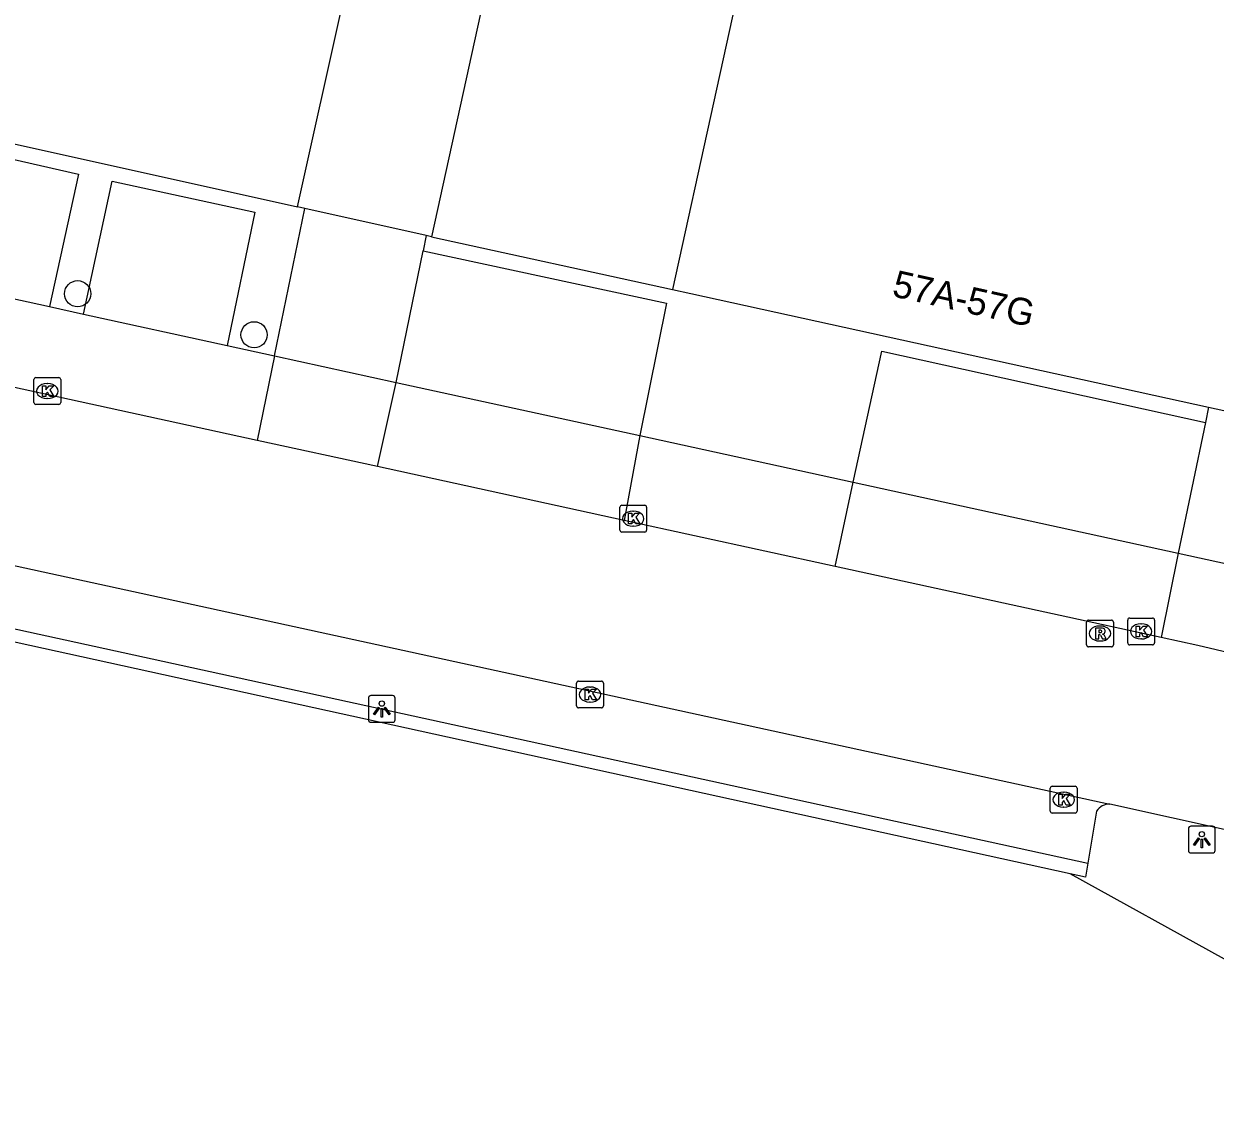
# Model space of a CAD drawing. Extents: x 163010 to 163853, y 382793 to 383982.
# Drawn here: x 163213.7 to 163258.14, y 382852.68 to 382893.41 of the extents above; entities that cross this region are included whole.
import ezdxf

# ---------------------------------------------------------------- set-up
doc = ezdxf.new("R2010")
doc.units = 0
for name, color, linetype in [('IMGEO_Boom', 7, 'Continuous'), ('IMGEO_Kademuur', 7, 'Continuous'), ('IMGEO_Kolk', 7, 'Continuous'), ('IMGEO_Lichtpunt', 7, 'Continuous'), ('IMGEO_Pand', 7, 'Continuous'), ('IMGEO_Pand_nummerreeks', 7, 'Continuous'), ('IMGEO_Parkeervlak_open', 7, 'Continuous'), ('IMGEO_Rijbaan_lokaal_open', 7, 'Continuous'), ('IMGEO_Rioolput', 7, 'Continuous'), ('IMGEO_Voetpad_open', 7, 'Continuous'), ('IMGEO_Waterloop', 7, 'Continuous')]:
    doc.layers.add(name, color=color, linetype=linetype)

msp = doc.modelspace()

# ---------------------------------------------------------------- linework, layer by layer
at = {"layer": 'IMGEO_Boom'}
for centre in [(163215.704, 382883.335), (163222.286, 382881.804)]:
    msp.add_circle(centre, 0.489, dxfattribs=at)
at = {"layer": 'IMGEO_Kademuur'}
for points in [[(163252.738, 382861.689), (163209.827, 382871.108), (163204.433, 382869.162), (163201.933, 382869.794), (163192.517, 382871.853), (163191.906, 382871.987), (163186.047, 382873.165), (163185.933, 382872.633), (163174.194, 382875.226), (163171.373, 382875.849), (163171.404, 382875.989), (163170.403, 382876.218), (163170.06, 382876.294)], [(163209.526, 382871.666), (163253.391, 382862.084)], [(163253.391, 382862.084), (163253.303, 382861.565), (163252.738, 382861.689)]]:
    msp.add_lwpolyline(points, dxfattribs=at)
at = {"layer": 'IMGEO_Kolk'}
for p, q in [((163214.072, 382879.279), (163214.072, 382880.131)), ((163214.147, 382880.205), (163214.999, 382880.205)), ((163215.073, 382880.131), (163215.073, 382879.279)), ((163214.56, 382879.985), (163214.585, 382879.985)), ((163214.999, 382879.205), (163214.147, 382879.205)), ((163214.583, 382879.425), (163214.558, 382879.425)), ((163235.931, 382874.518), (163235.931, 382875.37)), ((163236.006, 382875.444), (163236.858, 382875.444)), ((163236.419, 382875.224), (163236.444, 382875.224)), ((163236.932, 382875.37), (163236.932, 382874.518)), ((163236.858, 382874.444), (163236.006, 382874.444)), ((163236.442, 382874.664), (163236.417, 382874.664)), ((163254.954, 382871.234), (163255.806, 382871.234)), ((163254.879, 382870.308), (163254.879, 382871.16)), ((163255.367, 382871.014), (163255.392, 382871.014)), ((163255.88, 382871.16), (163255.88, 382870.308)), ((163255.39, 382870.454), (163255.365, 382870.454)), ((163255.806, 382870.234), (163254.954, 382870.234)), ((163234.318, 382867.954), (163234.318, 382868.806)), ((163234.393, 382868.88), (163235.245, 382868.88)), ((163234.806, 382868.66), (163234.831, 382868.66)), ((163235.319, 382868.806), (163235.319, 382867.954)), ((163234.829, 382868.1), (163234.804, 382868.1)), ((163235.245, 382867.88), (163234.393, 382867.88)), ((163251.991, 382864.03), (163251.991, 382864.882)), ((163252.066, 382864.956), (163252.918, 382864.956)), ((163252.479, 382864.736), (163252.504, 382864.736)), ((163252.992, 382864.882), (163252.992, 382864.03)), ((163252.502, 382864.176), (163252.477, 382864.176)), ((163252.918, 382863.956), (163252.066, 382863.956))]:
    msp.add_line(p, q, dxfattribs=at)
for points in [[(163214.072, 382879.279), (163214.072, 382880.131)], [(163214.147, 382880.205), (163214.999, 382880.205)], [(163215.073, 382880.131), (163215.073, 382879.279)], [(163214.393, 382879.905), (163214.516, 382879.905), (163214.516, 382879.754), (163214.646, 382879.905), (163214.81, 382879.905), (163214.664, 382879.754), (163214.817, 382879.505), (163214.665, 382879.505), (163214.58, 382879.669), (163214.516, 382879.602), (163214.516, 382879.505), (163214.393, 382879.505), (163214.393, 382879.905)], [(163214.999, 382879.205), (163214.147, 382879.205)], [(163235.931, 382874.518), (163235.931, 382875.37)], [(163236.006, 382875.444), (163236.858, 382875.444)], [(163236.932, 382875.37), (163236.932, 382874.518)], [(163236.252, 382875.144), (163236.375, 382875.144), (163236.375, 382874.993), (163236.505, 382875.144), (163236.669, 382875.144), (163236.523, 382874.993), (163236.676, 382874.744), (163236.524, 382874.744), (163236.439, 382874.908), (163236.375, 382874.841), (163236.375, 382874.744), (163236.252, 382874.744), (163236.252, 382875.144)], [(163236.858, 382874.444), (163236.006, 382874.444)], [(163254.954, 382871.234), (163255.806, 382871.234)], [(163254.879, 382870.308), (163254.879, 382871.16)], [(163255.2, 382870.934), (163255.323, 382870.934), (163255.323, 382870.783), (163255.453, 382870.934), (163255.617, 382870.934), (163255.471, 382870.783), (163255.624, 382870.534), (163255.472, 382870.534), (163255.387, 382870.698), (163255.323, 382870.631), (163255.323, 382870.534), (163255.2, 382870.534), (163255.2, 382870.934)], [(163255.88, 382871.16), (163255.88, 382870.308)], [(163255.806, 382870.234), (163254.954, 382870.234)], [(163234.318, 382867.954), (163234.318, 382868.806)], [(163234.393, 382868.88), (163235.245, 382868.88)], [(163234.639, 382868.58), (163234.762, 382868.58), (163234.762, 382868.429), (163234.892, 382868.58), (163235.056, 382868.58), (163234.91, 382868.429), (163235.063, 382868.18), (163234.911, 382868.18), (163234.826, 382868.344), (163234.762, 382868.277), (163234.762, 382868.18), (163234.639, 382868.18), (163234.639, 382868.58)], [(163235.319, 382868.806), (163235.319, 382867.954)], [(163235.245, 382867.88), (163234.393, 382867.88)], [(163251.991, 382864.03), (163251.991, 382864.882)], [(163252.066, 382864.956), (163252.918, 382864.956)], [(163252.312, 382864.656), (163252.435, 382864.656), (163252.435, 382864.505), (163252.565, 382864.656), (163252.729, 382864.656), (163252.583, 382864.505), (163252.736, 382864.256), (163252.584, 382864.256), (163252.499, 382864.42), (163252.435, 382864.353), (163252.435, 382864.256), (163252.312, 382864.256), (163252.312, 382864.656)], [(163252.992, 382864.882), (163252.992, 382864.03)], [(163252.918, 382863.956), (163252.066, 382863.956)]]:
    msp.add_lwpolyline(points, dxfattribs=at)
for centre, start, end in [((163214.149, 382880.129), 91.552, 178.448), ((163214.149, 382880.129), 91.552, 178.448), ((163214.997, 382880.129), 1.552, 88.448), ((163214.997, 382880.129), 1.552, 88.448), ((163214.149, 382879.281), 181.552, 268.448), ((163214.149, 382879.281), 181.552, 268.448), ((163214.997, 382879.281), 271.552, 358.448), ((163214.997, 382879.281), 271.552, 358.448), ((163236.008, 382875.368), 91.552, 178.448), ((163236.008, 382875.368), 91.552, 178.448), ((163236.856, 382875.368), 1.552, 88.448), ((163236.856, 382875.368), 1.552, 88.448), ((163236.008, 382874.52), 181.552, 268.448), ((163236.008, 382874.52), 181.552, 268.448), ((163236.856, 382874.52), 271.552, 358.448), ((163236.856, 382874.52), 271.552, 358.448), ((163254.956, 382871.158), 91.552, 178.448), ((163254.956, 382871.158), 91.552, 178.448), ((163255.804, 382871.158), 1.552, 88.448), ((163255.804, 382871.158), 1.552, 88.448), ((163254.956, 382870.31), 181.552, 268.448), ((163254.956, 382870.31), 181.552, 268.448), ((163255.804, 382870.31), 271.552, 358.448), ((163255.804, 382870.31), 271.552, 358.448), ((163234.395, 382868.804), 91.552, 178.448), ((163234.395, 382868.804), 91.552, 178.448), ((163235.243, 382868.804), 1.552, 88.448), ((163235.243, 382868.804), 1.552, 88.448), ((163234.395, 382867.956), 181.552, 268.448), ((163234.395, 382867.956), 181.552, 268.448), ((163235.243, 382867.956), 271.552, 358.448), ((163235.243, 382867.956), 271.552, 358.448), ((163252.068, 382864.88), 91.552, 178.448), ((163252.068, 382864.88), 91.552, 178.448), ((163252.916, 382864.88), 1.552, 88.448), ((163252.916, 382864.88), 1.552, 88.448), ((163252.068, 382864.032), 181.552, 268.448), ((163252.068, 382864.032), 181.552, 268.448), ((163252.916, 382864.032), 271.552, 358.448), ((163252.916, 382864.032), 271.552, 358.448)]:
    msp.add_arc(centre, 0.0765, start, end, dxfattribs=at)
for centre, major_axis, ratio, start_param, end_param in [((163214.559, 382879.705), (-0.387, 0.002), 0.722429, 4.712389, 7.853982), ((163214.584, 382879.705), (-0.39, 0.002), 0.717154, 1.570796, 4.712389), ((163236.418, 382874.944), (-0.387, 0.002), 0.722429, 4.712389, 7.853982), ((163236.443, 382874.944), (-0.39, 0.002), 0.717154, 1.570796, 4.712389), ((163255.366, 382870.734), (-0.387, 0.002), 0.722429, 4.712389, 7.853982), ((163255.391, 382870.734), (-0.39, 0.002), 0.717154, 1.570796, 4.712389), ((163234.805, 382868.38), (-0.387, 0.002), 0.722429, 4.712389, 7.853982), ((163234.83, 382868.38), (-0.39, 0.002), 0.717154, 1.570796, 4.712389), ((163252.478, 382864.456), (-0.387, 0.002), 0.722429, 4.712389, 7.853982), ((163252.503, 382864.456), (-0.39, 0.002), 0.717154, 1.570796, 4.712389)]:
    msp.add_ellipse(centre, major_axis=major_axis, ratio=ratio, start_param=start_param, end_param=end_param, dxfattribs=at)
at = {"layer": 'IMGEO_Lichtpunt'}
for p, q in [((163226.554, 382868.245), (163226.554, 382867.438)), ((163226.554, 382868.245), (163226.554, 382867.438)), ((163227.456, 382868.34), (163226.648, 382868.34)), ((163227.456, 382868.34), (163226.648, 382868.34)), ((163227.55, 382867.438), (163227.55, 382868.245)), ((163227.55, 382867.438), (163227.55, 382868.245)), ((163226.648, 382867.344), (163227.456, 382867.344)), ((163226.648, 382867.344), (163227.456, 382867.344)), ((163257.146, 382863.37), (163257.146, 382862.563)), ((163257.146, 382863.37), (163257.146, 382862.563)), ((163258.048, 382863.465), (163257.24, 382863.465)), ((163258.048, 382863.465), (163257.24, 382863.465)), ((163258.142, 382862.563), (163258.142, 382863.37)), ((163258.142, 382862.563), (163258.142, 382863.37)), ((163257.24, 382862.469), (163258.048, 382862.469)), ((163257.24, 382862.469), (163258.048, 382862.469))]:
    msp.add_line(p, q, dxfattribs=at)
for points in [[(163226.928, 382867.909), (163226.967, 382867.881), (163226.779, 382867.619), (163226.741, 382867.646), (163226.928, 382867.909)], [(163227.03, 382867.861), (163227.077, 382867.861), (163227.077, 382867.539), (163227.03, 382867.539), (163227.03, 382867.861)], [(163227.14, 382867.881), (163227.178, 382867.908), (163227.365, 382867.646), (163227.326, 382867.618), (163227.14, 382867.881)], [(163257.52, 382863.034), (163257.559, 382863.006), (163257.371, 382862.744), (163257.333, 382862.771), (163257.52, 382863.034)], [(163257.622, 382862.986), (163257.669, 382862.986), (163257.669, 382862.664), (163257.622, 382862.664), (163257.622, 382862.986)], [(163257.732, 382863.006), (163257.77, 382863.033), (163257.957, 382862.771), (163257.918, 382862.743), (163257.732, 382863.006)]]:
    msp.add_lwpolyline(points, dxfattribs=at)
for centre in [(163227.053, 382868.043), (163257.645, 382863.168)]:
    msp.add_circle(centre, 0.0994, dxfattribs=at)
for centre, start, end in [((163226.648, 382868.245), 90, 180), ((163226.648, 382868.245), 90, 180), ((163227.456, 382868.245), 0, 90), ((163227.456, 382868.245), 0, 90), ((163226.648, 382867.438), 180, 270), ((163226.648, 382867.438), 180, 270), ((163227.456, 382867.438), 270, 0), ((163227.456, 382867.438), 270, 360), ((163257.24, 382863.37), 90, 180), ((163257.24, 382863.37), 90, 180), ((163258.048, 382863.37), 0, 90), ((163258.048, 382863.37), 0, 90), ((163257.24, 382862.563), 180, 270), ((163257.24, 382862.563), 180, 270), ((163258.048, 382862.563), 270, 0), ((163258.048, 382862.563), 270, 360)]:
    msp.add_arc(centre, 0.0946, start, end, dxfattribs=at)
at = {"layer": 'IMGEO_Pand'}
for points in [[(163244.014, 382911.371), (163237.897, 382883.491)], [(163223.9, 382886.575), (163229.114, 382910.023), (163234.048, 382908.941)], [(163234.048, 382908.941), (163228.901, 382885.463)], [(163196.54, 382892.658), (163223.9, 382886.575)], [(163228.901, 382885.463), (163237.897, 382883.491)], [(163237.897, 382883.491), (163238.577, 382883.342), (163257.896, 382879.106)], [(163257.896, 382879.106), (163259.319, 382878.794)]]:
    msp.add_lwpolyline(points, dxfattribs=at)
at = {"layer": 'IMGEO_Parkeervlak_open'}
msp.add_lwpolyline([(163253.719, 382864.029), (163253.391, 382862.084)], dxfattribs=at)
msp.add_arc((163254.2, 382863.709), 0.578, 88.8558, 146.3927, dxfattribs=at)
at = {"layer": 'IMGEO_Rijbaan_lokaal_open'}
for points in [[(163222.402, 382877.865), (163194.101, 382884.044)], [(163177.011, 382881.11), (163254.212, 382864.287)], [(163226.896, 382876.884), (163222.402, 382877.865)], [(163236.089, 382874.877), (163226.896, 382876.884)], [(163243.96, 382873.158), (163236.089, 382874.877)], [(163256.125, 382870.502), (163243.96, 382873.158)], [(163261.344, 382869.304), (163257.497, 382870.203), (163256.125, 382870.502)], [(163261.222, 382862.733), (163254.212, 382864.287)]]:
    msp.add_lwpolyline(points, dxfattribs=at)
at = {"layer": 'IMGEO_Rioolput'}
for p, q in [((163253.344, 382870.231), (163253.344, 382871.083)), ((163253.419, 382871.157), (163254.271, 382871.157)), ((163253.832, 382870.937), (163253.857, 382870.937)), ((163254.345, 382871.083), (163254.345, 382870.231)), ((163253.855, 382870.377), (163253.83, 382870.377)), ((163254.271, 382870.157), (163253.419, 382870.157))]:
    msp.add_line(p, q, dxfattribs=at)
for points in [[(163253.344, 382870.231), (163253.344, 382871.083)], [(163253.419, 382871.157), (163254.271, 382871.157)], [(163253.933, 382870.855), (163253.681, 382870.857), (163253.681, 382870.457)], [(163253.859, 382870.776), (163253.805, 382870.776), (163253.805, 382870.695)], [(163254.345, 382871.083), (163254.345, 382870.231)], [(163253.681, 382870.457), (163253.805, 382870.457), (163253.805, 382870.619), (163253.816, 382870.619)], [(163253.805, 382870.695), (163253.857, 382870.695)], [(163253.863, 382870.59), (163253.934, 382870.457), (163254.074, 382870.457), (163254.009, 382870.583)], [(163254.271, 382870.157), (163253.419, 382870.157)]]:
    msp.add_lwpolyline(points, dxfattribs=at)
for centre, radius, start, end in [((163253.421, 382871.081), 0.0765, 91.552, 178.448), ((163253.421, 382871.081), 0.0765, 91.552, 178.448), ((163253.865, 382870.68), 0.0964, 77.0061, 93.1865), ((163253.879, 382870.737), 0.0378, 276.6634, 79.6772), ((163253.932, 382870.745), 0.109, 350.3612, 89.416), ((163254.269, 382871.081), 0.0765, 1.552, 88.448), ((163254.269, 382871.081), 0.0765, 1.552, 88.448), ((163253.815, 382870.566), 0.0533, 26.0293, 88.6989), ((163253.841, 382870.884), 0.19, 274.7715, 282.9687), ((163253.93, 382870.745), 0.112, 277.5842, 350.9817), ((163253.914, 382870.53), 0.108, 29.5134, 73.7905), ((163253.421, 382870.233), 0.0765, 181.552, 268.448), ((163253.421, 382870.233), 0.0765, 181.552, 268.448), ((163254.269, 382870.233), 0.0765, 271.552, 358.448), ((163254.269, 382870.233), 0.0765, 271.552, 358.448)]:
    msp.add_arc(centre, radius, start, end, dxfattribs=at)
for centre, major_axis, ratio, start_param, end_param in [((163253.831, 382870.657), (-0.387, 0.002), 0.722429, 4.712389, 7.853982), ((163253.856, 382870.657), (-0.39, 0.002), 0.717154, 1.570796, 4.712389)]:
    msp.add_ellipse(centre, major_axis=major_axis, ratio=ratio, start_param=start_param, end_param=end_param, dxfattribs=at)
at = {"layer": 'IMGEO_Voetpad_open'}
for points in [[(163209.406, 382883.999), (163210.493, 382888.991), (163215.738, 382887.804), (163214.651, 382882.854)], [(163215.919, 382882.577), (163216.987, 382887.542), (163222.32, 382886.384), (163221.288, 382881.404)], [(163223.042, 382881.021), (163224.179, 382886.513)], [(163224.179, 382886.513), (163223.9, 382886.575)], [(163228.707, 382885.506), (163224.179, 382886.513)], [(163228.707, 382885.506), (163228.596, 382884.932)], [(163228.901, 382885.463), (163228.707, 382885.506)], [(163227.584, 382880.029), (163228.596, 382884.932)], [(163228.596, 382884.932), (163237.677, 382882.98), (163236.681, 382878.042)], [(163209.406, 382883.999), (163214.651, 382882.854)], [(163214.651, 382882.854), (163215.919, 382882.577)], [(163215.919, 382882.577), (163221.288, 382881.404)], [(163221.288, 382881.404), (163223.042, 382881.021)], [(163223.042, 382881.021), (163222.402, 382877.865)], [(163223.042, 382881.021), (163227.584, 382880.029)], [(163244.642, 382876.302), (163245.702, 382881.195), (163257.778, 382878.535)], [(163226.896, 382876.884), (163227.584, 382880.029)], [(163227.584, 382880.029), (163236.681, 382878.042)], [(163257.896, 382879.106), (163257.778, 382878.535)], [(163257.778, 382878.535), (163256.762, 382873.655)], [(163236.681, 382878.042), (163236.089, 382874.877)], [(163236.681, 382878.042), (163237.472, 382877.869), (163244.642, 382876.302)], [(163243.96, 382873.158), (163244.642, 382876.302)], [(163244.642, 382876.302), (163256.762, 382873.655)], [(163256.762, 382873.655), (163256.125, 382870.502)], [(163256.762, 382873.655), (163262.003, 382872.51)]]:
    msp.add_lwpolyline(points, dxfattribs=at)
at = {"layer": 'IMGEO_Waterloop'}
msp.add_lwpolyline([(163280.241, 382852.682), (163259.917, 382858.193), (163258.496, 382858.498), (163252.738, 382861.689)], dxfattribs=at)

# ---------------------------------------------------------------- texts
at = {"layer": 'IMGEO_Pand_nummerreeks'}
msp.add_text('57A-57G', height=1, rotation=347.435, dxfattribs=at).set_placement((163246.05, 382883.251))

doc.saveas('drawing.dxf')
